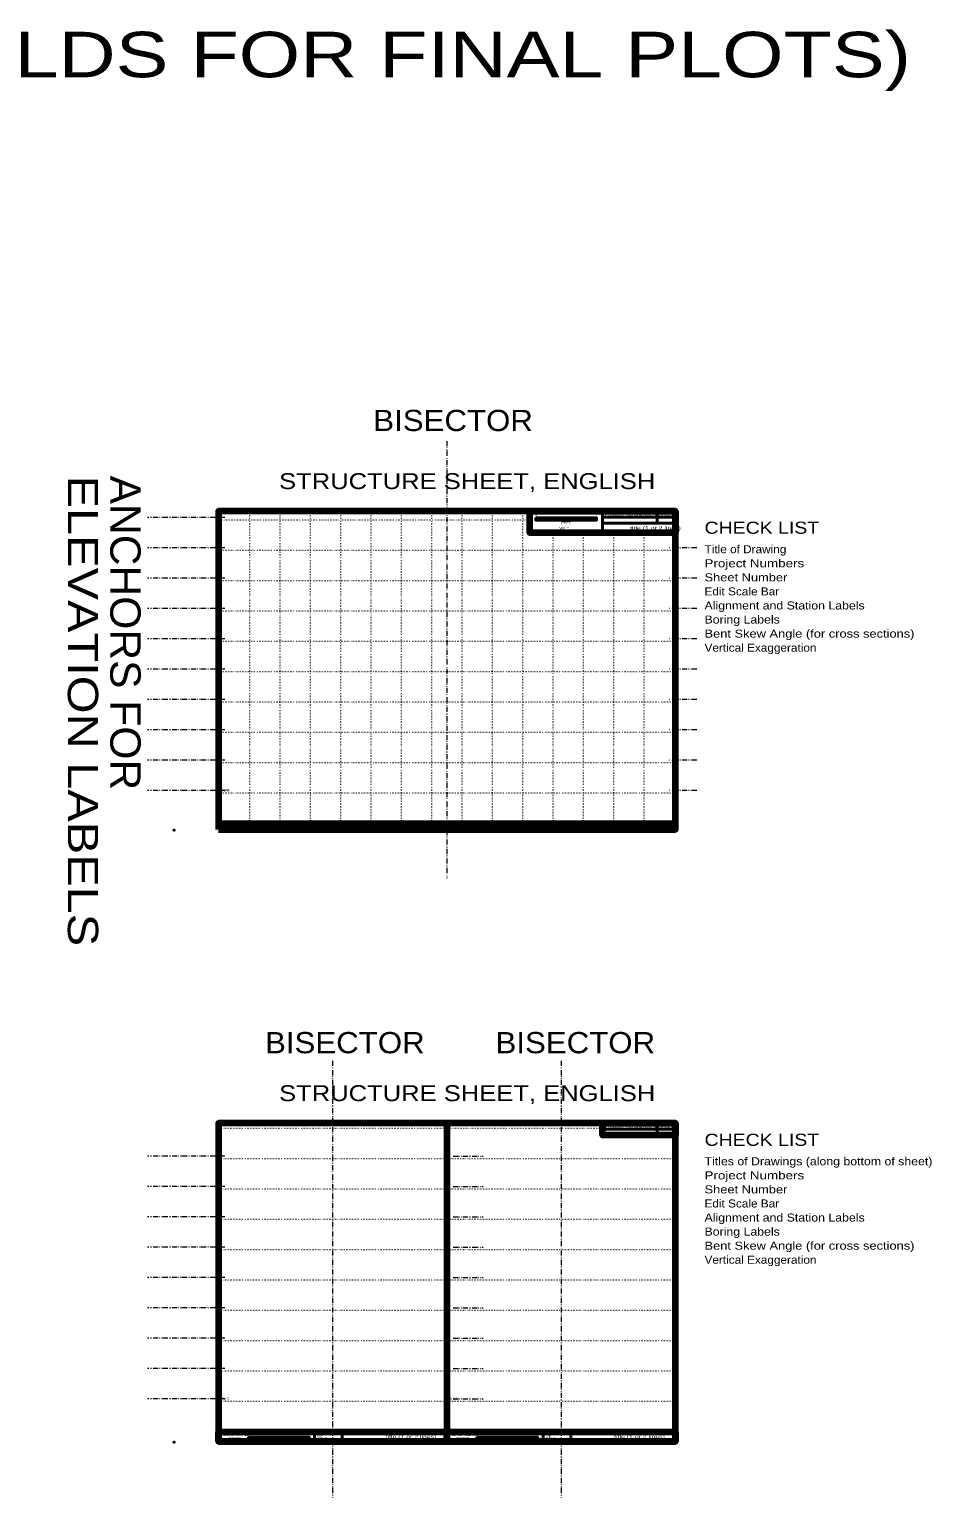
# Model space of a CAD drawing. Extents: x 278712 to 279914, y 171254 to 171792.
# Drawn here: x 279616.6 to 279914.1, y 171253.9 to 171738.1 of the extents above; entities that cross this region are included whole.
import ezdxf
from ezdxf.enums import TextEntityAlignment as Align

# ---------------------------------------------------------------- set-up
doc = ezdxf.new("R2010")
doc.units = 0
doc.header["$LTSCALE"] = 0.34
doc.header["$PDMODE"] = 32
doc.header["$PDSIZE"] = 0.17
doc.linetypes.add('DASH_DOUBLE_DOT', pattern=[9.2, 5, -1.2, 0.3, -1.2, 0.3, -1.2])
doc.linetypes.add('DOTTED', pattern=[1.5, 0.3, -1.2])
for name, color, linetype, lineweight in [('11', 7, 'DOTTED', 13), ('46', 7, 'DASH_DOUBLE_DOT', 13), ('6', 7, 'Continuous', 90), ('60', 7, 'Continuous', 35), ('62', 7, 'Continuous', 35)]:
    doc.layers.add(name, color=color, linetype=linetype, lineweight=lineweight)
doc.layers.add('12', color=7, linetype='Continuous')
doc.layers.add('61', color=7, linetype='Continuous')

msp = doc.modelspace()

# ---------------------------------------------------------------- linework, layer by layer
at = {"layer": '11'}
for p, q in [((279781.6109, 171576.203), (279678.8949, 171576.203)), ((279689.2529, 171476.203), (279689.2529, 171579.2032)), ((279699.2529, 171476.203), (279699.2529, 171579.2032)), ((279709.2529, 171476.203), (279709.2529, 171579.2032)), ((279719.2529, 171476.203), (279719.2529, 171579.2032)), ((279729.2529, 171476.203), (279729.2529, 171579.2032)), ((279739.2529, 171476.203), (279739.2529, 171579.2032)), ((279749.2529, 171476.203), (279749.2529, 171579.2032)), ((279759.2529, 171476.203), (279759.2529, 171579.2032)), ((279769.2529, 171476.203), (279769.2529, 171579.2032)), ((279779.2529, 171476.203), (279779.2529, 171579.2032)), ((279789.2529, 171476.203), (279789.2529, 171572.0032)), ((279799.2529, 171476.203), (279799.2529, 171572.0032)), ((279809.2529, 171476.203), (279809.2529, 171572.0032)), ((279819.2529, 171476.203), (279819.2529, 171572.0032)), ((279829.6109, 171566.203), (279678.8949, 171566.203)), ((279829.6109, 171556.203), (279678.8949, 171556.203)), ((279829.6109, 171546.203), (279678.8949, 171546.203)), ((279829.6109, 171536.203), (279678.8949, 171536.203)), ((279829.6109, 171526.203), (279678.8949, 171526.203)), ((279829.6109, 171516.203), (279678.8949, 171516.203)), ((279829.6109, 171506.203), (279678.8949, 171506.203)), ((279829.6109, 171496.203), (279678.8949, 171496.203)), ((279829.6109, 171486.203), (279678.8949, 171486.203)), ((279754.2529, 171375.556), (279678.8949, 171375.556)), ((279805.6109, 171375.556), (279754.2529, 171375.556)), ((279754.2529, 171365.556), (279678.8949, 171365.556)), ((279829.6109, 171365.556), (279754.2529, 171365.556)), ((279754.2529, 171355.556), (279678.8949, 171355.556)), ((279829.6109, 171355.556), (279754.2529, 171355.556)), ((279754.2529, 171345.556), (279678.8949, 171345.556)), ((279829.6109, 171345.556), (279754.2529, 171345.556)), ((279754.2529, 171335.556), (279678.8949, 171335.556)), ((279829.6109, 171335.556), (279754.2529, 171335.556)), ((279754.2529, 171325.556), (279678.8949, 171325.556)), ((279829.6109, 171325.556), (279754.2529, 171325.556)), ((279754.2529, 171315.556), (279678.8949, 171315.556)), ((279829.6109, 171315.556), (279754.2529, 171315.556)), ((279754.2529, 171305.556), (279678.8949, 171305.556)), ((279829.6109, 171305.556), (279754.2529, 171305.556)), ((279754.2529, 171295.556), (279678.8949, 171295.556)), ((279829.6109, 171295.556), (279754.2529, 171295.556)), ((279754.2529, 171285.556), (279678.8949, 171285.556)), ((279829.6109, 171285.556), (279754.2529, 171285.556))]:
    msp.add_line(p, q, dxfattribs=at)
at = {"layer": '46'}
for p, q in [((279754.2529, 171602.281), (279754.2529, 171458.2032)), ((279680.9761, 171577.0995), (279655.4866, 171577.0995)), ((279680.9761, 171567.0995), (279655.4866, 171567.0995)), ((279836.6161, 171567.0995), (279827.5296, 171567.0995)), ((279680.9761, 171557.0995), (279655.4866, 171557.0995)), ((279836.6161, 171557.0995), (279827.5296, 171557.0995)), ((279680.9761, 171547.0995), (279655.4866, 171547.0995)), ((279836.6161, 171547.0995), (279827.5296, 171547.0995)), ((279680.9761, 171537.0995), (279655.4866, 171537.0995)), ((279836.6161, 171537.0995), (279827.5296, 171537.0995)), ((279680.9761, 171527.0995), (279655.4866, 171527.0995)), ((279836.6161, 171527.0995), (279827.5296, 171527.0995)), ((279680.9761, 171517.0995), (279655.4866, 171517.0995)), ((279836.6161, 171517.0995), (279827.5296, 171517.0995)), ((279680.9761, 171507.0995), (279655.4866, 171507.0995)), ((279836.6161, 171507.0995), (279827.5296, 171507.0995)), ((279680.9761, 171497.0995), (279655.4866, 171497.0995)), ((279836.6161, 171497.0995), (279827.5296, 171497.0995)), ((279680.9761, 171487.0995), (279655.4866, 171487.0995)), ((279836.6161, 171487.0995), (279827.5296, 171487.0995)), ((279716.5739, 171397.941), (279716.5739, 171253.8632)), ((279791.9319, 171397.941), (279791.9319, 171253.8632)), ((279680.9761, 171366.4525), (279655.4866, 171366.4525)), ((279756.3341, 171366.4525), (279766.1611, 171366.4525)), ((279680.9761, 171356.4525), (279655.4866, 171356.4525)), ((279756.3341, 171356.4525), (279766.1611, 171356.4525)), ((279680.9761, 171346.4525), (279655.4866, 171346.4525)), ((279756.3341, 171346.4525), (279766.1611, 171346.4525)), ((279680.9761, 171336.4525), (279655.4866, 171336.4525)), ((279756.3341, 171336.4525), (279766.1611, 171336.4525)), ((279680.9761, 171326.4525), (279655.4866, 171326.4525)), ((279756.3341, 171326.4525), (279766.1611, 171326.4525)), ((279680.9761, 171316.4525), (279655.4866, 171316.4525)), ((279756.3341, 171316.4525), (279766.1611, 171316.4525)), ((279680.9761, 171306.4525), (279655.4866, 171306.4525)), ((279756.3341, 171306.4525), (279766.1611, 171306.4525)), ((279680.9761, 171296.4525), (279655.4866, 171296.4525)), ((279756.3341, 171296.4525), (279766.1611, 171296.4525)), ((279680.9761, 171286.4525), (279655.4866, 171286.4525)), ((279756.3341, 171286.4525), (279766.1611, 171286.4525))]:
    msp.add_line(p, q, dxfattribs=at)
at = {"layer": '6'}
msp.add_line((279678.8949, 171476.203), (279829.6109, 171476.203), dxfattribs=at)
at = {"layer": '60', "lineweight": 40}
for p, q in [((279805.6109, 171579.2032), (279805.6106, 171572.0032)), ((279805.6109, 171577.2032), (279829.6109, 171577.2032)), ((279823.6109, 171579.2032), (279823.6109, 171575.2032)), ((279805.6109, 171575.2032), (279829.6109, 171575.2032)), ((279805.6109, 171572.0032), (279829.6109, 171572.0032)), ((279805.6109, 171377.356), (279805.6109, 171373.356)), ((279823.6109, 171377.356), (279823.6109, 171373.356)), ((279805.6109, 171375.356), (279829.6109, 171375.356)), ((279805.6109, 171373.356), (279829.6109, 171373.356)), ((279710.5989, 171275.5557), (279710.5989, 171272.3557)), ((279719.7624, 171275.5557), (279719.7624, 171272.3557)), ((279730.2529, 171272.3557), (279754.2529, 171272.3557)), ((279785.9569, 171275.5557), (279785.9569, 171272.3557)), ((279795.1204, 171275.5557), (279795.1204, 171272.3557)), ((279805.6109, 171272.3557), (279829.6109, 171272.3557))]:
    msp.add_line(p, q, dxfattribs=at)
at = {"layer": '60', "lineweight": 90}
msp.add_line((279754.2529, 171377.356), (279754.2529, 171272.3557), dxfattribs=at)
for points in [[(279678.8949, 171474.203), (279829.6109, 171474.203), (279829.6109, 171579.2032), (279678.8949, 171579.2032)], [(279781.6109, 171579.2032), (279829.6109, 171579.2032), (279829.6109, 171572.0032), (279781.6109, 171572.0032)], [(279678.8949, 171272.3557), (279829.6109, 171272.3557), (279829.6109, 171377.356), (279678.8949, 171377.356)], [(279805.6109, 171377.356), (279829.6109, 171377.356), (279829.6109, 171373.356), (279805.6109, 171373.356)], [(279678.8949, 171275.556), (279754.2529, 171275.5557), (279754.2529, 171272.3555), (279678.8949, 171272.3557)], [(279754.2529, 171275.556), (279829.6109, 171275.5557), (279829.6109, 171272.3555), (279754.2529, 171272.3557)]]:
    msp.add_lwpolyline(points, close=True, dxfattribs=at)
at = {"layer": '60'}
for points in [[(279783.6109, 171577.1217), (279803.6109, 171577.1217), (279803.6109, 171576.1217), (279783.6109, 171576.1217)], [(279783.6109, 171577.1217), (279793.6109, 171577.1217), (279793.6109, 171576.6217), (279783.6109, 171576.6217)], [(279793.6109, 171576.6217), (279803.6109, 171576.6217), (279803.6109, 171576.1217), (279793.6109, 171576.1217)], [(279688.7921, 171273.8697), (279708.7921, 171273.8697), (279708.7921, 171272.8697), (279688.7921, 171272.8697)], [(279688.7921, 171273.8697), (279698.7921, 171273.8697), (279698.7921, 171273.3697), (279688.7921, 171273.3697)], [(279698.7921, 171273.3697), (279708.7921, 171273.3697), (279708.7921, 171272.8697), (279698.7921, 171272.8697)], [(279764.1501, 171273.8697), (279784.1501, 171273.8697), (279784.1501, 171272.8697), (279764.1501, 171272.8697)], [(279764.1501, 171273.8697), (279774.1501, 171273.8697), (279774.1501, 171273.3697), (279764.1501, 171273.3697)], [(279774.1501, 171273.3697), (279784.1501, 171273.3697), (279784.1501, 171272.8697), (279774.1501, 171272.8697)]]:
    msp.add_lwpolyline(points, close=True, dxfattribs=at)
for p in [(279829.7801, 171579.421), (279664.2866, 171473.985), (279829.7801, 171377.5737), (279664.2866, 171272.138)]:
    msp.add_point(p, dxfattribs=at)

# ---------------------------------------------------------------- texts
at = {"layer": '12', "width": 1.2}
for p in [(279681.1755, 171486.5995), (279681.1755, 171285.9525), (279756.5335, 171285.9525)]:
    msp.add_text('###', height=1, dxfattribs=at).set_placement(p, align=Align.CENTER)
at = {"layer": '60'}
for s, height, width, p in [('STRUCTURE SHEET, ENGLISH', 5.25, 1.2, (279760.938, 171586.465)), ('0', 0.84, 0.9, (279783.6474, 171577.5972)), ('PROJECT REFERENCE NO.', 0.9, 1.15, (279815.5445, 171577.7532)), ('VE =  ', 0.84, 1.35, (279793.3542, 171573.1545)), ('FEET', 0.84, 1.1, (279793.5894, 171574.9037)), ('title (1 or 2 lines) ', 1.167, 1.45, (279823.3364, 171573.02)), ('STRUCTURE SHEET, ENGLISH', 5.25, 1.2, (279760.938, 171384.6177)), ('PROJECT REFERENCE NO.', 0.9, 1.15, (279815.5445, 171375.9059)), ('HORIZ. SCALE', 0.84, 1.25, (279684.4376, 171274.1557)), ('(FEET)', 0.84, 1.3, (279684.1235, 171272.9157)), ('0', 0.84, 0.9, (279688.8286, 171274.3455)), ('title (1 or 2 lines) ', 1.167, 1.45, (279742.7329, 171273.3725)), ('HORIZ. SCALE', 0.84, 1.25, (279759.7956, 171274.1557)), ('(FEET)', 0.84, 1.3, (279759.4815, 171272.9157)), ('0', 0.84, 0.9, (279764.1865, 171274.3455)), ('title (1 or 2 lines) ', 1.167, 1.45, (279818.0912, 171273.3725))]:
    msp.add_text(s, height=height, dxfattribs=dict(at, width=width)).set_placement(p, align=Align.CENTER)
for p in [(279826.5854, 171577.7532), (279826.5854, 171375.9059)]:
    msp.add_text('SHEET', height=0.9, dxfattribs=at).set_placement(p, align=Align.CENTER)
for s, height, width, p in [('CHECK LIST', 4, 1.2, (279839.2011, 171571.7227)), ('Title of Drawing', 2.64, 1.1, (279839.2011, 171565.3225)), ('Project Numbers', 2.64, 1.25, (279839.2011, 171560.6825)), ('Sheet Number', 2.64, 1.2, (279839.2011, 171556.0425)), ('Edit Scale Bar', 2.64, 1.1, (279839.2011, 171551.4025)), ('Alignment and Station Labels', 2.64, 1.15, (279839.2011, 171546.7625)), ('Boring Labels', 2.64, 1.15, (279839.2011, 171542.1225)), ('Bent Skew Angle (for cross sections)', 2.64, 1.2, (279839.2011, 171537.4825)), ('Vertical Exaggeration', 2.64, 1.1, (279839.2011, 171532.8425)), ('CHECK LIST', 4, 1.2, (279839.2011, 171369.8755)), ('Titles of Drawings (along bottom of sheet)', 2.64, 1.15, (279839.2011, 171363.4752)), ('Project Numbers', 2.64, 1.25, (279839.2011, 171358.8352)), ('Sheet Number', 2.64, 1.2, (279839.2011, 171354.1952)), ('Edit Scale Bar', 2.64, 1.1, (279839.2011, 171349.5552)), ('Alignment and Station Labels', 2.64, 1.15, (279839.2011, 171344.9152)), ('Boring Labels', 2.64, 1.15, (279839.2011, 171340.2752)), ('Vertical Exaggeration', 2.64, 1.1, (279839.2011, 171330.9952)), ('Bent Skew Angle (for cross sections)', 2.64, 1.2, (279839.2011, 171335.6352)), ('VE =  ', 0.84, 1.35, (279711.4446, 171273.5357)), ('VE =  ', 0.84, 1.35, (279786.8029, 171273.5357))]:
    msp.add_text(s, height=height, dxfattribs=dict(at, width=width)).set_placement(p)
at = {"layer": '61', "width": 1.3}
msp.add_text('(TURN OFF DRAFTING AID LEVELS and DATA FIELDS FOR FINAL PLOTS)', height=15, dxfattribs=at).set_placement((278998.7991, 171722.2772))
at = {"layer": '62', "width": 1.1}
for p in [(279729.9649, 171605.6), (279694.2734, 171400.4137), (279770.2706, 171400.4137)]:
    msp.add_text('BISECTOR', height=7, dxfattribs=at).set_placement(p)
at = {"layer": '62'}
for s, width, p in [('ANCHORS FOR', 1.05, (279643.2496, 171590.915)), ('ELEVATION LABELS', 1.2, (279629.2496, 171590.915))]:
    msp.add_text(s, height=10, rotation=270, dxfattribs=dict(at, width=width)).set_placement(p)

doc.saveas('drawing.dxf')
